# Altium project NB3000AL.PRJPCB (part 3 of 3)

## Sheet CON_FFC40_LCDTFT.SCHDOC: LCD Module Connector
size A4; DocumentNumber: 63; Revision: 01; SheetNumber: 64; SheetTotal: 78
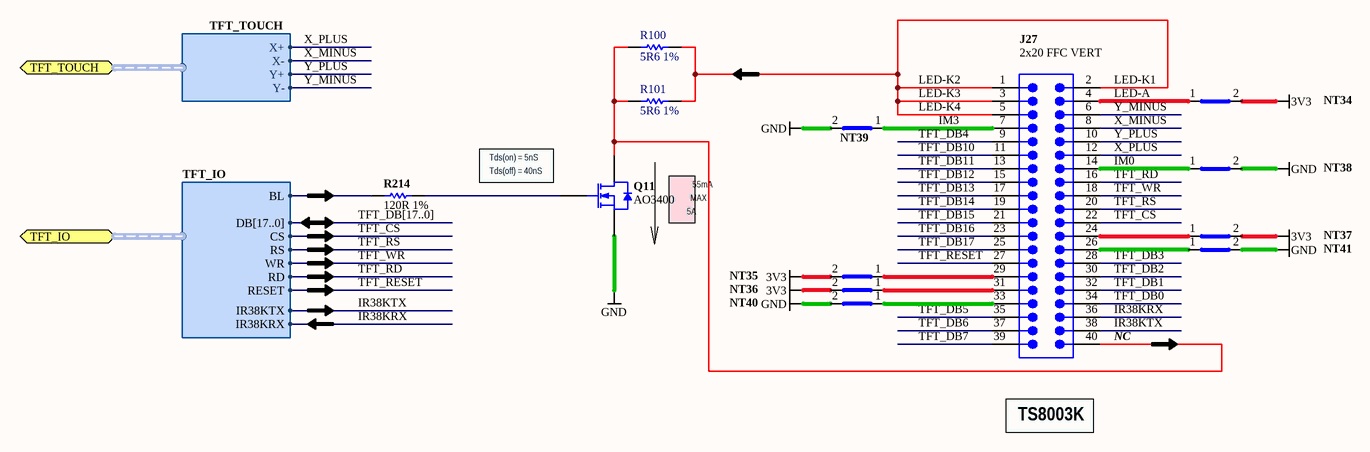
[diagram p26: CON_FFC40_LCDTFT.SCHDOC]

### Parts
J27  2x20 FFC VERT  [FPC-xxS1VN3R]
NT34  Net Tie SMT2  [NETTIE-SMT2-8X8]  (value not drawn)  (net tie, no BOM)
NT35  Net Tie SMT2  [NETTIE-SMT2-8X8]  (value not drawn)  (net tie, no BOM)
NT36  Net Tie SMT2  [NETTIE-SMT2-8X8]  (value not drawn)  (net tie, no BOM)
NT37  Net Tie SMT2  [NETTIE-SMT2-8X8]  (value not drawn)  (net tie, no BOM)
NT38  Net Tie SMT2  [NETTIE-SMT2-8X8]  (value not drawn)  (net tie, no BOM)
NT39  Net Tie SMT2  [NETTIE-SMT2-8X8]  (value not drawn)  (net tie, no BOM)
NT40  Net Tie SMT2  [NETTIE-SMT2-8X8]  (value not drawn)  (net tie, no BOM)
NT41  Net Tie SMT2  [NETTIE-SMT2-8X8]  (value not drawn)  (net tie, no BOM)
Q11  AO3400  [SOT95P230-3D]
R100  5R6 1%  [RESC1005-STAR]
R101  5R6 1%  [RESC1005-STAR]
R214  120R 1%  [RESC1005-STAR]

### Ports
TFT_IO (harness TFT_IO), TFT_TOUCH (harness TFT_TOUCH)

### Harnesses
TFT_IO: CS, RS, WR, RD, RESET, DB[17..0], BL, IR38KTX, IR38KRX
TFT_TOUCH: X+, X-, Y+, Y-

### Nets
3V3: NT34.2(Net2) NT35.2(Net2) NT36.2(Net2) NT37.2(Net2)
GND: NT38.2(Net2) NT39.2(Net2) NT40.2(Net2) NT41.2(Net2) Q11.3(S)
IR38KRX: J27.36 ; port TFT_IO.IR38KRX
IR38KTX: J27.38 ; port TFT_IO.IR38KTX
TFT_CS: J27.22 ; port TFT_IO.CS
TFT_DB0: J27.34
TFT_DB1: J27.32
TFT_DB2: J27.30
TFT_DB3: J27.28
TFT_DB4: J27.9
TFT_DB5: J27.35
TFT_DB6: J27.37
TFT_DB7: J27.39
TFT_DB10: J27.11
TFT_DB11: J27.13
TFT_DB12: J27.15
TFT_DB13: J27.17
TFT_DB14: J27.19
TFT_DB15: J27.21
TFT_DB16: J27.23
TFT_DB17: J27.25
TFT_RD: J27.16 ; port TFT_IO.RD
TFT_RESET: J27.27 ; port TFT_IO.RESET
TFT_RS: J27.20 ; port TFT_IO.RS
TFT_WR: J27.18 ; port TFT_IO.WR
X_MINUS: J27.8 ; port TFT_TOUCH.X-
X_PLUS: J27.12 ; port TFT_TOUCH.X+
Y_MINUS: J27.6 ; port TFT_TOUCH.Y-
Y_PLUS: J27.10 ; port TFT_TOUCH.Y+
NetJ27_1: J27.1 J27.2 J27.3 J27.5 R100.1 R101.1
NetJ27_4: J27.4 NT34.1(Net1)
NetJ27_7: J27.7 NT39.1(Net1)
NetJ27_14: J27.14 NT38.1(Net1)
NetJ27_24: J27.24 NT37.1(Net1)
NetJ27_26: J27.26 NT41.1(Net1)
NetJ27_29: J27.29 NT35.1(Net1)
NetJ27_31: J27.31 NT36.1(Net1)
NetJ27_33: J27.33 NT40.1(Net1)
NetJ27_40: J27.40 Q11.2(D) R100.2 R101.2
NetQ11_1: Q11.1(G) R214.1
NetR214_2: R214.2 ; port TFT_IO.BL

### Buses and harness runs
bus TFT_DB[17..0]

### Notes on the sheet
- LED-K3
- LED-K2
- LED-K4
- (near NT39) IM3
- LED-K1
- LED-A
- (near Q11) Tds(on) = 5nS
- (near Q11) Tds(off) = 40nS
- 55mA
- (near J27) IM0
- 5A
- MAX
- (near J27) NC
- TS8003K

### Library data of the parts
J27 = D-300-0125: Header FFC, 2x20 pin Vertical, 0.5mm; Connector type: Straight; Max Current: mA
NT34-NT41 = D-002-0003: Net-Tie, Surface Mount, 2 x 1.6mm x 0.8mm SMT Pads - For 0.8mm Track
Q11 = D-158-0005: N-channel Enhancement Mode Field-effect Transistor;  5.8A/30V; Transistor Type: NPN
R100 R101 = D-100-0085: Resistor, 5R6 1% 0402 (1005); Power Rating: 63mW; Resistance: 5.6R
R214 = D-100-0126: Resistor, 120R 1% 0402 (1005); Power Rating: 63 mW

## Sheet Mounts.SchDoc: NB3000AL Holes and Graphics
size A4; Organization: Altium Limited.; DocumentNumber: 19; Revision: 6; SheetNumber: 20; SheetTotal: 78
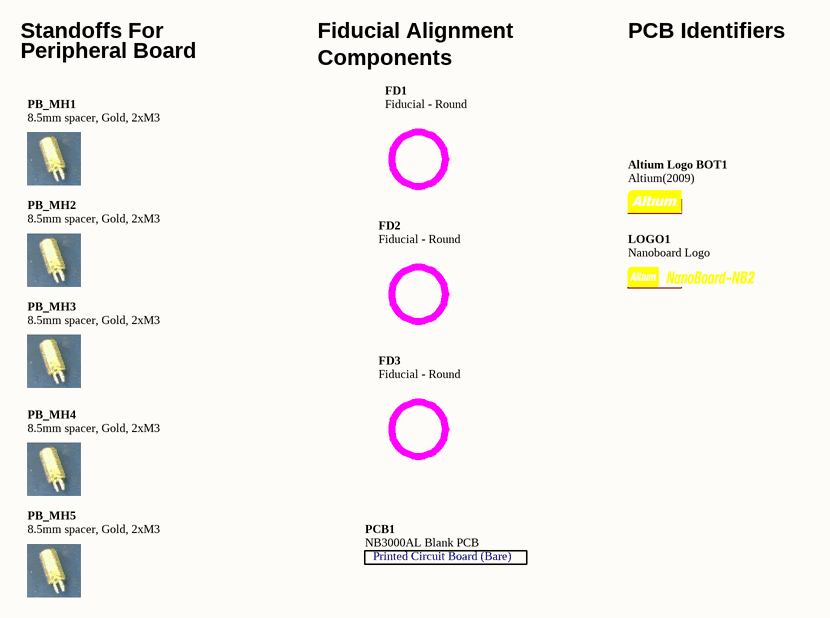
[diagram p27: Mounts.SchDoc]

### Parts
Altium_Logo_BOT1  Altium(2009)  [Logo-Altium-New]  (no BOM)
FD1  Fiducial - Round  [FIDUCIAL ROUND]  (no BOM)
FD2  Fiducial - Round  [FIDUCIAL ROUND]  (no BOM)
FD3  Fiducial - Round  [FIDUCIAL ROUND]  (no BOM)
LOGO1  Nanoboard Logo  [NANOBOARD LOGO]  (no BOM)
PB_MH1  8.5mm spacer, Gold, 2xM3  [STANDOFF_SOLDER_3MM]
PB_MH2  8.5mm spacer, Gold, 2xM3  [STANDOFF_SOLDER_3MM]
PB_MH3  8.5mm spacer, Gold, 2xM3  [STANDOFF_SOLDER_3MM]
PB_MH4  8.5mm spacer, Gold, 2xM3  [STANDOFF_SOLDER_3MM]
PB_MH5  8.5mm spacer, Gold, 2xM3  [STANDOFF_SOLDER_3MM]
PCB1  NB3000AL Blank PCB

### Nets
SHIELD: PB_MH1.STAND PB_MH2.STAND PB_MH3.STAND PB_MH4.STAND PB_MH5.STAND

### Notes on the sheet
- Peripheral Board
- Standoffs For
- Fiducial Alignment
- Components
- PCB Identifiers

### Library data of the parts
Altium_Logo_BOT1 = D-000-0003: Altium Logo for PCB
FD1-FD3 = D-004-0001: Fiducial - Round 1.5mm Top-Bottom
LOGO1 = D-000-0000
PB_MH1-PB_MH5 = D-306-0001: Spacer, 8.5mm GOLD, Splitted bottom, Female M3-thread
PCB1 = D-810-0053: NB3000AL Blank PCB - NanoBoard  3000 Series with Altera Cyclone3; ProjectPath: NB3000AL.PrjPCB

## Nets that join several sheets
1V2: PSU (TP7.1), USER_DECOUPLING_CAPS_1V2 (12 pins), USER_DECOUPLING_CAPS_3V3 (14 pins), FPGA_NonIO (54 pins), HOST_FPGA_NonIO (10 pins), HOST_DECOUPLING_CAPS_1V2 (12 pins), HOST_DECOUPLING_CAPS_3V3 (14 pins)
2V5: PSU (TP5.1), FPGA_NonIO (L4.1 L5.1 L6.1 L7.1), HOST_FPGA_NonIO (L8.1 L9.1)
3V3: VIDEO_DAC_THS8134B (C1#1.1 U1#2.12 U1#2.23 U1#2.24), Audio_Codec (R98.2 R154#1.2 U2000.4), PSU (TP4.1), FPGA (11 pins), USER_DECOUPLING_CAPS_3V3 (32 pins), FPGA_NonIO (60 pins), Ethernet_RTL8201CL (19 pins), Host_FPGA (6 pins), HOST_FPGA_NonIO (30 pins), HOST_DECOUPLING_CAPS_3V3 (32 pins), TSC_XPT2046 (R2#6.1), USB_CY7C68001-56LFC (19 pins), OSC_24MHZ (C3#5.1 U1#5.5), CON_FFC40_LCDTFT (NT34.2 NT35.2 NT36.2 NT37.2)
5V0: VIDEO_DAC_THS8134B (L1#1.1), PSU (6 pins), PWJACK+SWITCH (SW1.1 SW1.2), TSC_XPT2046 (NT9.2)
+B: PSU (TP3.1), PWJACK+SWITCH (D10.2 J1#2.1 SW1.3)
AUGND: PSU (NT1#1.1), CON_AUDIO_AC99_NOMIC (J1#4.1 J3#2.1 J4.1 J5.1)
GND: VGA_OUT (U1#1.2), VIDEO_DAC_THS8134B (17 pins), Audio_Codec (U2000.1), PSU (16 pins), FPGA (6 pins), USER_DECOUPLING_CAPS_1V2 (12 pins), USER_DECOUPLING_CAPS_3V3 (46 pins), FPGA_NonIO (135 pins), PULLDOWN (R284A.1 R285A.1 R286A.1), PULLDOWN (R284B.1 R285B.1 R286B.1), PULLDOWN (R284C.1 R285C.1 R286C.1), PULLDOWN (R284D.1 R285D.1 R286D.1), PULLDOWN (R284E.1 R285E.1 R286E.1), PULLDOWN (R284F.1 R285F.1 R286F.1), PULLDOWN (R284G.1 R285G.1 R286G.1), PULLDOWN (R284H.1 R285H.1 R286H.1), PWJACK+SWITCH (D10.1 J1#2.2 J1#2.3), Ethernet_RTL8201CL (50 pins), HOST_JTAG (J1#3.9 J1#3.10), Host_FPGA (R271.2 U69.2), HOST_FPGA_NonIO (43 pins), HOST_DECOUPLING_CAPS_1V2 (12 pins), HOST_DECOUPLING_CAPS_3V3 (46 pins), PULLDOWN (R284I.1 R285I.1 R286I.1), PULLDOWN (R284J.1 R285J.1 R286J.1), TSC_XPT2046 (NT11#2.1 U1#4.6 U1#4.7 U1#4.8), USB_CY7C68001-56LFC (21 pins), OSC_24MHZ (6 pins), CON_FFC40_LCDTFT (5 pins)
SHIELD: PSU (C169.1 R248.1), PWJACK+SWITCH (SW1.S1 SW1.S2), Mounts (5 pins)
An_B: VGA_OUT (U1#1.3), VIDEO_DAC_THS8134B (R2#1.1 R3#1.2 U1#2.45)
An_G: VGA_OUT (U1#1.4), VIDEO_DAC_THS8134B (R4#1.1 R5#1.2 U1#2.41)
An_R: VGA_OUT (U1#1.1), VIDEO_DAC_THS8134B (R6#1.2 R7#1.2 U1#2.43)
CONF_DONE: FPGA (R22#1.2), FPGA_NonIO (U8.P24)
DCLK: FPGA (R20#1.2), FPGA_NonIO (U8.P3)
FLASH_BOOT_CLK: Host_FPGA (U30.L6), HOST_FPGA_NonIO (U30.H1)
LED0_B: FPGA (U8.R3), PULLDOWN (R284A.2)
LED0_G: FPGA (U8.U1), PULLDOWN (R285A.2)
LED0_R: FPGA (U8.R2), PULLDOWN (R286A.2)
LED1_B: FPGA (U8.V4), PULLDOWN (R284B.2)
LED1_BLUE: Host_FPGA (U30.R7), PULLDOWN (R284I.2)
LED1_G: FPGA (U8.T3), PULLDOWN (R285B.2)
LED1_GREEN: Host_FPGA (U30.K8), PULLDOWN (R285I.2)
LED1_R: FPGA (U8.W9), PULLDOWN (R286B.2)
LED1_RED: Host_FPGA (U30.F5), PULLDOWN (R286I.2)
LED2_B: FPGA (U8.AD10), PULLDOWN (R284C.2)
LED2_BLUE: Host_FPGA (U30.B1), PULLDOWN (R284J.2)
LED2_G: FPGA (U8.AG11), PULLDOWN (R285C.2)
LED2_GREEN: Host_FPGA (U30.R9), PULLDOWN (R285J.2)
LED2_R: FPGA (U8.AC10), PULLDOWN (R286C.2)
LED2_RED: Host_FPGA (U30.C2), PULLDOWN (R286J.2)
LED3_B: FPGA (U8.AD11), PULLDOWN (R284D.2)
LED3_G: FPGA (U8.AC12), PULLDOWN (R285D.2)
LED3_R: FPGA (U8.Y13), PULLDOWN (R286D.2)
LED4_B: FPGA (U8.AB23), PULLDOWN (R284E.2)
LED4_G: FPGA (U8.AD26), PULLDOWN (R285E.2)
LED4_R: FPGA (U8.AB24), PULLDOWN (R286E.2)
LED5_B: FPGA (U8.AB20), PULLDOWN (R284F.2)
LED5_G: FPGA (U8.AA24), PULLDOWN (R285F.2)
LED5_R: FPGA (U8.AB25), PULLDOWN (R286F.2)
LED6_B: FPGA (U8.AA25), PULLDOWN (R284G.2)
LED6_G: FPGA (U8.AA23), PULLDOWN (R285G.2)
LED6_R: FPGA (U8.W26), PULLDOWN (R286G.2)
LED7_B: FPGA (U8.AD27), PULLDOWN (R284H.2)
LED7_G: FPGA (U8.AC28), PULLDOWN (R285H.2)
LED7_R: FPGA (U8.Y22), PULLDOWN (R286H.2)
nCONFIG: FPGA (R24#1.2), FPGA_NonIO (U8.P4)
nSTATUS: FPGA (R18#1.1), FPGA_NonIO (U8.M6)
TCK: FPGA (R9#1.2), FPGA_NonIO (U8.P5)
TDI: FPGA (R12#1.2), FPGA_NonIO (U8.P7)
TDO: FPGA (R10#1.2), FPGA_NonIO (U8.P6)
TMS: FPGA (R8#1.2), FPGA_NonIO (U8.P8)

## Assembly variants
Production: not fitted RN1 RN2 RN3 RN4 RN5 RN6 RN7 RN8 RN17 RN18 RN19 RN20 RN21 RN22 RN23 RN24 RN25 RN26 RN27 RN28 RN29 RN30 RN31 RN32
